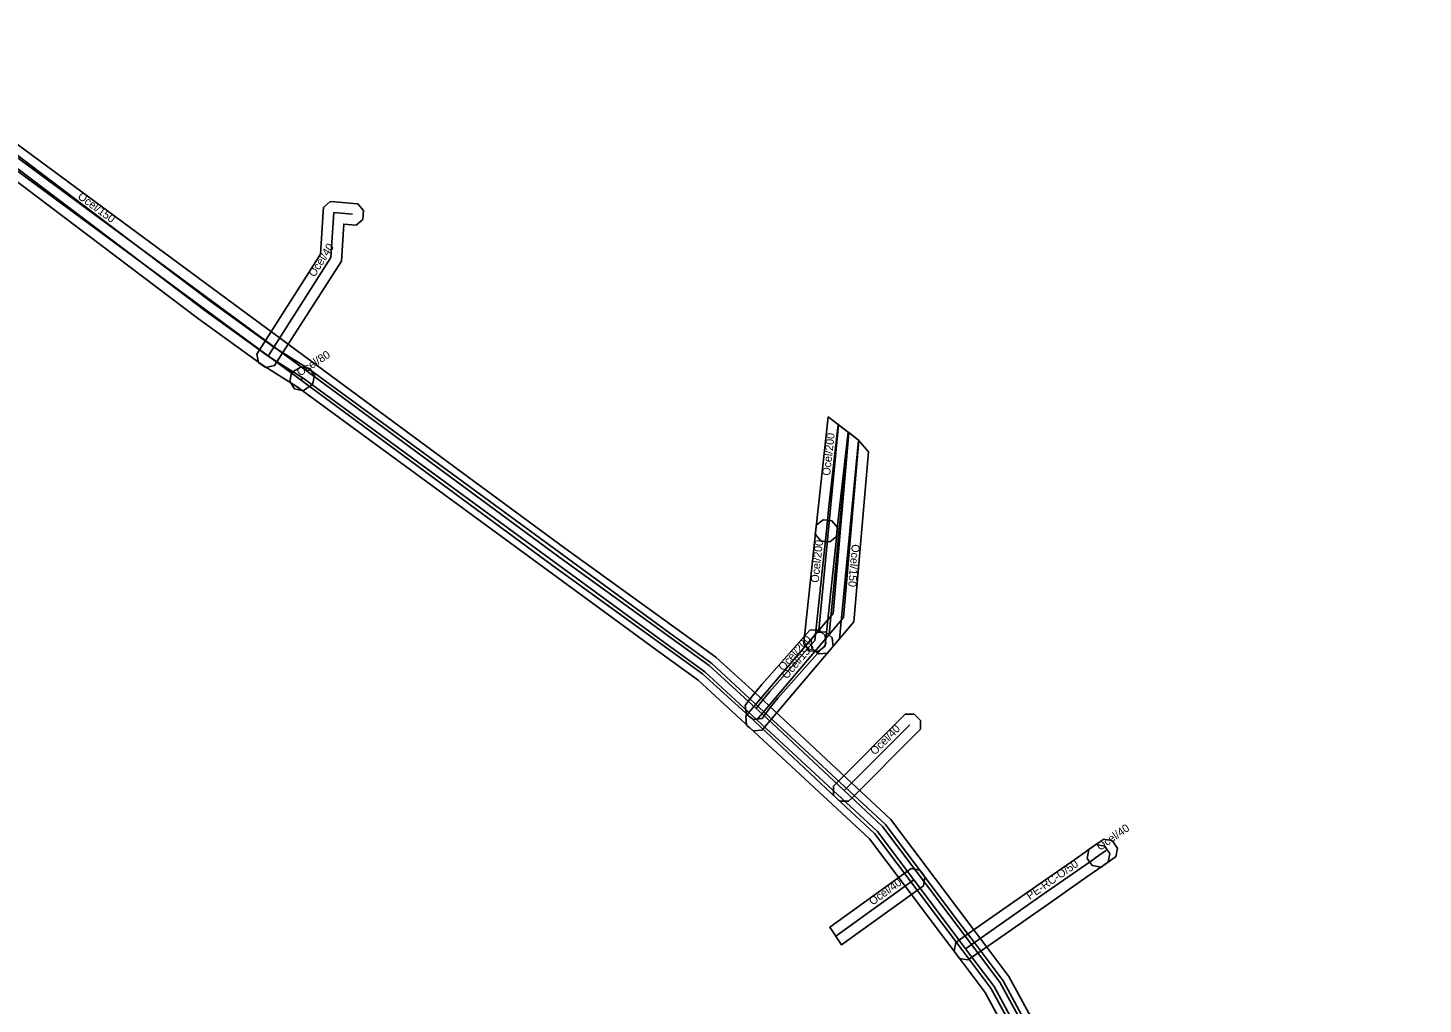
# Model space of a CAD drawing. Extents: x -749340 to -748632, y -965391 to -964902.
# Drawn here: x -748807.4 to -748676.6, y -965299.9 to -965208.4 of the extents above; entities that cross this region are included whole.
import ezdxf

# ---------------------------------------------------------------- set-up
doc = ezdxf.new("R2010")
doc.units = 0
for name, color, linetype in [('1', 7, 'Continuous'), ('15', 7, 'Continuous'), ('18', 7, 'Continuous'), ('20', 7, 'Continuous'), ('24', 7, 'Continuous'), ('28', 7, 'Continuous'), ('30', 7, 'Continuous'), ('51', 7, 'Continuous')]:
    doc.layers.add(name, color=color, linetype=linetype)

msp = doc.modelspace()

# ---------------------------------------------------------------- linework, layer by layer
at = {"layer": '1'}
for points in [[(-748824.19, -965208.44), (-748797.89, -965228.31), (-748790.22, -965234.1), (-748784.34, -965238.35), (-748781.05, -965240.41), (-748747.24, -965265.16), (-748743.32, -965268), (-748738.42, -965272.53), (-748727.04, -965283.07), (-748723.58, -965287.66), (-748720.19, -965292.18), (-748718.73, -965294.11), (-748716.01, -965297.73), (-748706.19, -965315.89)], [(-748707.95, -965316.84), (-748717.7, -965298.81), (-748720.33, -965295.31), (-748721.78, -965293.38), (-748725.18, -965288.86), (-748728.53, -965284.41), (-748739.77, -965274), (-748744.58, -965269.55), (-748748.42, -965266.78), (-748782.17, -965242.07), (-748785.46, -965240.01), (-748791.41, -965235.71), (-748799.1, -965229.9), (-748825.4, -965210.03)], [(-748816.06, -965213.71), (-748766.07, -965250.55), (-748757.07, -965257.18), (-748742.93, -965267.41), (-748738.46, -965271.46), (-748737.92, -965271.97), (-748730.22, -965279.17), (-748726.57, -965282.59), (-748718.18, -965293.71), (-748715.47, -965297.31), (-748708.2, -965310.65)], [(-748709.95, -965311.6), (-748717.16, -965298.4), (-748719.78, -965294.92), (-748728.06, -965283.93), (-748731.59, -965280.63), (-748739.29, -965273.43), (-748739.82, -965272.93), (-748744.19, -965268.97), (-748758.25, -965258.8), (-748767.26, -965252.16), (-748817.24, -965215.32)]]:
    msp.add_lwpolyline(points, dxfattribs=at)
for points in [[(-748776.64, -965226.91), (-748777.05, -965226.88), (-748777.8, -965226.82), (-748778.02, -965230.28), (-748784.06, -965239.72), (-748784.28, -965240.07), (-748785.09, -965240.25), (-748785.44, -965240.03), (-748785.79, -965239.8), (-748785.96, -965238.99), (-748785.74, -965238.65), (-748779.99, -965229.64), (-748779.73, -965225.68), (-748779.71, -965225.26), (-748779.39, -965224.98), (-748779.07, -965224.71), (-748778.65, -965224.74), (-748776.89, -965224.89), (-748776.48, -965224.92), (-748775.94, -965225.55), (-748775.97, -965225.96), (-748776.01, -965226.38)], [(-748780.73, -965241.86), (-748781.08, -965242.08), (-748781.26, -965242.2), (-748781.61, -965242.43), (-748782.42, -965242.25), (-748782.64, -965241.9), (-748782.87, -965241.55), (-748782.69, -965240.74), (-748782.34, -965240.52), (-748782.15, -965240.4), (-748781.8, -965240.18), (-748780.99, -965240.35), (-748780.77, -965240.7), (-748780.55, -965241.05)], [(-748733.32, -965253.18), (-748732.4, -965244.89), (-748730.54, -965246.3), (-748731.34, -965253.4), (-748731.58, -965255.66), (-748731.62, -965256.08), (-748732.26, -965256.6), (-748732.67, -965256.55), (-748733.09, -965256.51), (-748733.61, -965255.87), (-748733.56, -965255.45)], [(-748729.58, -965247.03), (-748728.61, -965248.15), (-748729.99, -965264.1), (-748732.22, -965266.71), (-748732.48, -965267.03), (-748733.31, -965267.09), (-748733.63, -965266.83), (-748733.94, -965266.56), (-748734.01, -965265.73), (-748733.74, -965265.42), (-748731.93, -965263.29), (-748730.46, -965246.36)], [(-748734.69, -965266.15), (-748734.65, -965265.73), (-748733.56, -965255.45), (-748733.52, -965255.04), (-748732.88, -965254.52), (-748732.46, -965254.56), (-748732.05, -965254.61), (-748731.53, -965255.25), (-748731.57, -965255.66), (-748732.66, -965265.95), (-748732.7, -965266.36), (-748733.34, -965266.88), (-748733.76, -965266.83), (-748734.17, -965266.79)], [(-748740.19, -965271.93), (-748739.94, -965271.59), (-748739.49, -965271.01), (-748738.63, -965269.95), (-748734.4, -965265.18), (-748734.12, -965264.87), (-748733.3, -965264.82), (-748732.99, -965265.09), (-748732.68, -965265.37), (-748732.63, -965266.19), (-748732.9, -965266.5), (-748737.11, -965271.25), (-748737.92, -965272.24), (-748738.34, -965272.8), (-748738.59, -965273.13), (-748739.41, -965273.24), (-748739.74, -965272.99), (-748740.07, -965272.74)], [(-748731.95, -965266.4), (-748732.22, -965266.71), (-748738.33, -965273.91), (-748738.6, -965274.23), (-748739.43, -965274.3), (-748739.74, -965274.03), (-748740.06, -965273.76), (-748740.12, -965272.94), (-748739.86, -965272.62), (-748733.74, -965265.42), (-748733.47, -965265.1), (-748732.65, -965265.03), (-748732.33, -965265.3), (-748732.02, -965265.57)], [(-748731.9, -965279.49), (-748731.61, -965279.2), (-748725.47, -965273.03), (-748725.18, -965272.74), (-748724.35, -965272.74), (-748724.06, -965273.03), (-748723.76, -965273.32), (-748723.76, -965274.15), (-748724.05, -965274.45), (-748730.2, -965280.61), (-748730.49, -965280.9), (-748731.32, -965280.9), (-748731.61, -965280.61), (-748731.9, -965280.32)], [(-748720.44, -965294.13), (-748720.1, -965293.89), (-748717.7, -965292.21), (-748712.94, -965288.89), (-748709.3, -965286.35), (-748708.32, -965285.66), (-748707.81, -965285.3), (-748707.65, -965285.19), (-748707.31, -965284.95), (-748706.49, -965285.1), (-748706.26, -965285.44), (-748706.02, -965285.78), (-748706.16, -965286.59), (-748706.5, -965286.83), (-748706.66, -965286.94), (-748707.17, -965287.3), (-748708.16, -965287.99), (-748711.8, -965290.53), (-748716.55, -965293.85), (-748718.96, -965295.53), (-748719.3, -965295.77), (-748720.11, -965295.62), (-748720.35, -965295.28), (-748720.59, -965294.94)], [(-748707.99, -965285.43), (-748707.65, -965285.19), (-748707.62, -965285.17), (-748706.97, -965284.72), (-748706.93, -965284.69), (-748706.58, -965284.45), (-748705.77, -965284.6), (-748705.53, -965284.94), (-748705.3, -965285.28), (-748705.45, -965286.1), (-748705.79, -965286.33), (-748705.83, -965286.36), (-748706.47, -965286.81), (-748706.49, -965286.83), (-748706.83, -965287.07), (-748707.65, -965286.93), (-748707.89, -965286.59), (-748708.13, -965286.25)], [(-748723.8, -965289.07), (-748731.14, -965294.36), (-748732.26, -965292.7), (-748724.97, -965287.45), (-748724.63, -965287.21), (-748723.81, -965287.34), (-748723.57, -965287.68), (-748723.33, -965288.01), (-748723.46, -965288.83)]]:
    msp.add_lwpolyline(points, close=True, dxfattribs=at)
at = {"layer": '15'}
for points in [[(-748731.47, -965245.59), (-748732.33, -965253.29), (-748732.57, -965255.56)], [(-748730.49, -965246.34), (-748732.31, -965265.27), (-748732.98, -965266.06)], [(-748732.57, -965255.56), (-748733.65, -965265.84)]]:
    msp.add_lwpolyline(points, dxfattribs=at)
at = {"layer": '18'}
for points in [[(-748824.79, -965209.23), (-748798.49, -965229.11), (-748790.82, -965234.91), (-748784.9, -965239.18), (-748781.61, -965241.24), (-748747.83, -965265.97), (-748743.95, -965268.77), (-748739.09, -965273.27), (-748727.78, -965283.74), (-748724.38, -965288.26), (-748720.98, -965292.78), (-748719.53, -965294.71), (-748716.86, -965298.27), (-748707.07, -965316.36), (-748706.63, -965317.17), (-748698.53, -965332.16), (-748697.87, -965333.38), (-748692.28, -965343.72), (-748690.95, -965346.33), (-748688.89, -965350.39), (-748688.12, -965351.69), (-748686.59, -965354.32), (-748678.05, -965369.87)], [(-748776.97, -965225.88), (-748778.73, -965225.74), (-748779.01, -965229.96), (-748784.36, -965238.34), (-748784.9, -965239.18)], [(-748781.61, -965241.24), (-748781.8, -965241.36)], [(-748729.52, -965247.1), (-748730.96, -965263.69), (-748732.98, -965266.06)], [(-748732.98, -965266.06), (-748739.09, -965273.27)], [(-748707.07, -965286.01), (-748707.04, -965285.99), (-748706.4, -965285.54), (-748706.36, -965285.51)], [(-748719.53, -965294.71), (-748717.12, -965293.03), (-748712.37, -965289.71), (-748708.73, -965287.17), (-748707.74, -965286.48), (-748707.23, -965286.12), (-748707.07, -965286.01)], [(-748731.7, -965293.53), (-748724.38, -965288.26)]]:
    msp.add_lwpolyline(points, dxfattribs=at)
at = {"layer": '24'}
for points in [[(-748731.47, -965245.59), (-748732.33, -965253.29), (-748732.57, -965255.56)], [(-748730.9, -965279.9), (-748724.76, -965273.74)]]:
    msp.add_lwpolyline(points, dxfattribs=at)
at = {"layer": '28'}
for points in [[(-748816.65, -965214.51), (-748766.66, -965251.35), (-748757.66, -965257.99), (-748743.56, -965268.19), (-748739.14, -965272.2), (-748738.6, -965272.7), (-748730.9, -965279.9), (-748727.31, -965283.26), (-748718.98, -965294.32), (-748716.31, -965297.86), (-748709.08, -965311.12), (-748696.92, -965333.61), (-748686.2, -965353.68), (-748679.38, -965366.28), (-748676.65, -965371.4)], [(-748733.65, -965265.84), (-748732.57, -965255.56)], [(-748739.14, -965272.2), (-748738.71, -965271.63), (-748737.87, -965270.6), (-748733.65, -965265.84)]]:
    msp.add_lwpolyline(points, dxfattribs=at)
at = {"layer": '51'}
for points in [[(-748733.32, -965253.18), (-748732.4, -965244.89), (-748730.54, -965246.3), (-748731.34, -965253.4), (-748731.58, -965255.66), (-748731.62, -965256.08), (-748732.26, -965256.6), (-748732.67, -965256.55), (-748733.09, -965256.51), (-748733.61, -965255.87), (-748733.56, -965255.45)], [(-748729.58, -965247.03), (-748729.55, -965247.06), (-748731.34, -965265.68), (-748732.22, -965266.71), (-748732.48, -965267.03), (-748733.31, -965267.09), (-748733.63, -965266.83), (-748733.94, -965266.56), (-748734.01, -965265.73), (-748733.74, -965265.42), (-748733.27, -965264.86), (-748731.43, -965245.63)], [(-748731.53, -965255.25), (-748731.57, -965255.66), (-748732.66, -965265.95), (-748732.7, -965266.36), (-748733.34, -965266.88), (-748733.76, -965266.83), (-748734.17, -965266.79), (-748734.69, -965266.15), (-748734.65, -965265.73), (-748733.56, -965255.45), (-748733.52, -965255.04), (-748732.88, -965254.52), (-748732.46, -965254.56), (-748732.05, -965254.61)]]:
    msp.add_lwpolyline(points, close=True, dxfattribs=at)

# ---------------------------------------------------------------- texts
at = {"layer": '20'}
for s, rotation, p in [('Ocel/40', 57.4215, (-748780.54, -965231.84)), ('Ocel/80', 32.4712, (-748781.91, -965241.1)), ('Ocel/150', 265.0345, (-748730.18, -965256.79)), ('Ocel/150', 49.6657, (-748736.27, -965269.5)), ('Ocel/40', 34.9319, (-748706.92, -965285.56)), ('PE-RC-O/50', 34.9313, (-748713.5, -965290.16)), ('Ocel/40', 35.7546, (-748728.24, -965290.69))]:
    msp.add_text(s, height=0.75, rotation=rotation, dxfattribs=at).set_placement(p)
at = {"layer": '30'}
for s, rotation, p in [('Ocel/150', 323.611, (-748802.8, -965224.37)), ('Ocel/200', 83.6228, (-748732.23, -965250.42)), ('Ocel/200', 83.9977, (-748733.3, -965260.45)), ('Ocel/200', 48.436, (-748736.6, -965268.75)), ('Ocel/40', 45.0931, (-748728.03, -965276.62))]:
    msp.add_text(s, height=0.75, rotation=rotation, dxfattribs=at).set_placement(p)

doc.saveas('drawing.dxf')
